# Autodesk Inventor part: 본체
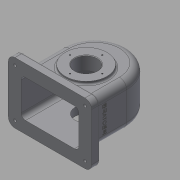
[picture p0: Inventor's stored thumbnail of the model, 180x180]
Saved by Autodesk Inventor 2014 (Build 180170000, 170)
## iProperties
Created: 2016-10
Part Number: 본체
Material: 일반
Document SubType Name: Modeling
Designer: SCD-A13
Density: 1 g/cm^3
Appearance: 기본값
Author: SCD-A13
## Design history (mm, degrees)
sketch "스케치1"
  geometry: L1 (-32.5, -38.5)-(32.5, -38.5); L2 (32.5, -38.5)-(32.5, 38.5); L3 (32.5, 38.5)-(-32.5, 38.5); L4 (-32.5, 38.5)-(-32.5, -38.5); L5 (-32.5, -38.5)-(32.5, 38.5); L6 (32.5, -38.5)-(-32.5, 38.5); 1 further point
  constraints: 12 end point, 2 midpoint, 2 parallel, 1 horizontal, 1 perpendicular
  dimensions: "d0" = 65 distance of L3.end L2.end; "d1" = 77 distance of L2.end L1.end
extrude "돌출1" new body sketch "스케치1" stored distance "d2" = 116; taper "d3" = 0 deg
sketch "스케치2"
  geometry: L1 (-58, 32.5)-(58, 32.5) reference; A1 r 58 centre (0, 32.5) between (58, 32.5) and (-58, 32.5); 1 further point
  constraints: 2 point on circle, 1 centre point
  dimensions: "d4" = 58 radius of A1
extrude "돌출2" join sketch "스케치2" stored distance "d5" = 77; taper "d6" = 0 deg
feature "쉘1" dims "d13" = 6
sketch "스케치13"
  geometry: L1 (32.5, -32.5)-(-32.5, -32.5) reference; L2 (-32.5, 32.5)-(32.5, 32.5) reference; L3 (-32.5, 33.5)-(32.5, 33.5); L4 (32.5, -33.5)-(-32.5, -33.5); L5 (32.5, 33.5)-(32.5, 32.5); L6 (-32.5, 33.5)-(-32.5, 32.5); L7 (-32.5, -32.5)-(-32.5, -33.5); L8 (32.5, -32.5)-(32.5, -33.5); 1 further point
  constraints: 12 end point, 3 equal length, 1 perpendicular
  dimensions: "d73" = 1 distance between parallel lines of L3 L2; "d74" = 1 distance between parallel lines of L4 L1
extrude "돌출7" cut sketch "스케치13" stored distance "d75" = 104; taper "d76" = 0 deg
sketch "스케치14"
  geometry: L1 (104, -1)-(0, -1) reference; L2 (52, -33.5)-(52, -1); L3 (104, -67)-(0, -67) reference; L4 (104, 0)-(52, 0); L5 (52, 0)-(52, -67); L6 (52, -67)-(104, -67); L7 (104, -67)-(104, 0)
  constraints: 10 end point, 2 midpoint, 2 parallel, 1 horizontal, 1 perpendicular
revolve "회전3" sketch "스케치14" stored, may be unused: angle "d77" = 180 deg
sketch "스케치3"
  geometry: L1 (0, 0)-(116, 0) reference; L2 (0, 0)-(0, 65) reference; L3 (0, 50)-(116, 50); C1 r 37.5 at (58, 50); 1 further point
  constraints: 2 end point, 1 centre point, 1 midpoint, 1 parallel
  dimensions: "d7" = 50 distance between parallel lines of L1 L3; "d8" = 75 diameter of C1; "d9" = 58 distance from line of L2 C1.centre
extrude "돌출3" join sketch "스케치3" distance "d10" = 5; taper "d11" = 0 deg
sketch "스케치4"
  geometry: L1 (-32.5, -38.5)-(-32.5, 38.5) reference; L2 (17.5, -38.5)-(17.5, 48.654); L3 (55, 43.5)-(-20, 43.5) reference; L4 (37.5, 33.5)-(37.5, 19.5); L5 (37.5, 19.5)-(45.5, 19.5); L6 (45.5, 19.5)-(57.247, 33.5); L7 (57.247, 33.5)-(37.5, 33.5); L8 (84.5, 33.5)-(32.5, 33.5) reference; 1 further point
  constraints: 10 end point, 2 perpendicular, 2 point on line, 1 parallel
  dimensions: "d12" = 50 distance between parallel lines of L1 L2; "d14" = 14 distance of L4.start L4.end; "d15" = 40 diameter of L4.end L2; "d16" = 50 deg angle of L5 L6; "d17" = 56 diameter of L5.end L2
revolve "회전1" sketch "스케치4" stored, may be unused: angle "d18" = 90 deg
sketch "스케치5"
  geometry: L1 (-32.5, -32.5)-(-32.5, 32.5) reference; L2 (17.5, 44.656)-(17.5, -39.016); L3 (37.5, 19.5)-(37.5, 33.5) reference; L4 (-2.5, 19.5)-(-2.5, 33.5) reference; L5 (55, 43.5)-(-20, 43.5) reference; L6 (32.5, -38.5)-(-32.5, -38.5) reference; L7 (37.5, 43.5)-(17.5, 43.5); L8 (17.5, 43.5)-(17.5, -38.5); L9 (17.5, -38.5)-(37.5, -38.5); L10 (37.5, -38.5)-(37.5, 43.5); 1 further point
  constraints: 10 end point, 4 point on line, 3 parallel, 1 horizontal, 1 perpendicular
  dimensions: "d78" = 50 distance between parallel lines of L1 L2
revolve "회전2" sketch "스케치5" stored, may be unused: angle "d21" = 90 deg
sketch "스케치6"
  geometry: C1 r 20 at (58, 50) reference; C2 r 31 at (58, 50); 1 further point
  constraints: 1 centre point, 1 coincident
  dimensions: "d22" = 62 diameter of C2
extrude "돌출4" join sketch "스케치6" distance "d23" = 10; taper "d24" = 0 deg
sketch "스케치7" dims "d25" = 52
  geometry: L1 (0, 0)-(0, 26); C1 r 20 at (0, 0) reference; 2 further points
  constraints: 2 coincident, 2 end point, 1 vertical, 1 vertical alignment, 2 other
hole "구멍1" sketch "스케치7" at (0, 26) diameter "d26" = 2.459; stored, may be unused: countersink angle "d30" = 90 deg, drill point angle "d32" = 118 deg; dims "d27" = 6, "d28" = 4, "d29" = 2, "d31" = 8
sketch "스케치8" dims "d33" = 58
  geometry: L1 (0, 0)-(0, 29); C1 r 37.5 at (0, 0) reference; 1 further point
  constraints: 2 end point, 1 coincident, 1 vertical, 1 vertical alignment, 2 other
hole "구멍2" sketch "스케치8" at (0, 29) diameter "d34" = 2.459; stored, may be unused: countersink angle "d38" = 90 deg, drill point angle "d40" = 118 deg; dims "d35" = 6, "d36" = 4, "d37" = 2, "d39" = 8
sketch "스케치9"
  geometry: L1 (133, -16.5)-(-17, -16.5); L2 (-17, -16.5)-(-17, 93.5); L3 (-17, 93.5)-(133, 93.5); L4 (133, 93.5)-(133, -16.5); L5 (133, -16.5)-(-17, 93.5); L6 (-17, -16.5)-(133, 93.5); L7 (6, 6)-(110, 71); L8 (110, 6)-(6, 71); L9 (6, 72)-(110, 72); L10 (110, 72)-(110, 5); L11 (110, 5)-(6, 5); L12 (6, 5)-(6, 72); 1 further point
  constraints: 24 end point, 4 midpoint, 4 parallel, 2 horizontal, 2 perpendicular
  dimensions: "d44" = 150 distance of L2.end L3.end; "d45" = 110 distance of L1.end L2.end
extrude "돌출5" join sketch "스케치9" distance "d46" = 15; taper "d47" = 0 deg
node "작업 평면1"
sketch "스케치10"
  geometry: C1 r 6 at (58, 38.5); 1 further point
  constraints: 1 centre point, 1 coincident
  dimensions: "d49" = 12 diameter of C1
extrude "돌출6" join sketch "스케치10" stored distance "d50" = 15; taper "d51" = 10 deg
sketch "스케치11"
  geometry: C1 r 6 at (0, 0) reference; 1 further point
  constraints: 1 coincident
hole "구멍3" sketch "스케치11" at (0, 0) diameter "d52" = 4.459; stored, may be unused: countersink angle "d56" = 90 deg, drill point angle "d58" = 118 deg; dims "d53" = 30, "d54" = 4, "d55" = 2, "d57" = 8
sketch "스케치12"
  geometry: L1 (121, -81.5)-(-5, -81.5); L2 (-5, -81.5)-(-5, 4.5); L3 (-5, 4.5)-(121, 4.5); L4 (121, 4.5)-(121, -81.5); L5 (121, -81.5)-(-5, 4.5); L6 (-5, -81.5)-(121, 4.5); 1 further point
  constraints: 12 end point, 2 midpoint, 2 parallel, 1 horizontal, 1 perpendicular
  dimensions: "d59" = 126 distance of L2.end L3.end; "d60" = 86 distance of L1.end L2.end
hole "구멍4" sketch "스케치12" at (-5, -81.5), (-5, 4.5), (121, 4.5), (121, -81.5) diameter "d61" = 5; stored, may be unused: countersink angle "d65" = 90 deg, drill point angle "d67" = 0 deg; dims "d62" = 30, "d63" = 12, "d64" = 5, "d66" = 8
fillet "모깎기1" dims "d68" = 12
fillet "모깎기3" dims "d70" = 13
fillet "모깎기4" dims "d79" = 8
chamfer "모따기1" distance "d80" = 1; stored, may be unused: second distance "d81" = 2, angle "d82" = 45 deg
fillet "모깎기5" dims "d83" = 3
node "작업 평면2"
sketch "스케치15"
  geometry: L1 (-47.5, -43)-(-47.5, 43) reference; L2 (32.5, 38.5)-(-29.5, 38.5) reference; 2 further points
  constraints: 1 other
  dimensions: "d85" = 38.5 distance from line of L2 point (-7.5, 0); "d86" = 40 distance from line of L1 point (-7.5, 0)
feature "엠보싱1" sketch "스케치15" dims "d0" = 65, "d1" = 77, "d7" = 50, "d8" = 75, "d9" = 58, "d87" = 0.5, "d88" = 0
node "솔리드1"
pattern_circular "원형 패턴1" dims angle "d42" = 360 deg
other parameters: "d48" = -144
